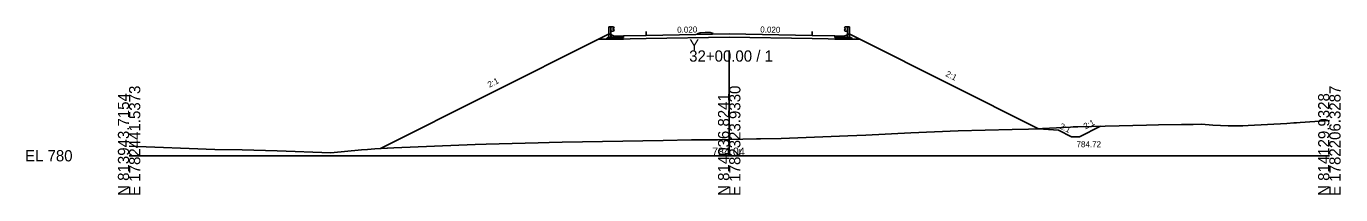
# Model space of a CAD drawing. Extents: x -12583 to 5303, y -44 to 25667.
# Drawn here: x 1974.3 to 2302.8, y 2490.3 to 2532.3 of the extents above; entities that cross this region are included whole.
import ezdxf

# ---------------------------------------------------------------- set-up
doc = ezdxf.new("R2010")
doc.units = 0
for name, color, linetype in [('Exist Cross Section Cell', 7, 'Continuous'), ('Exist XS Center Line Elevation Label', 7, 'Continuous'), ('Exist XS Ground Line', 7, 'Continuous'), ('Prop Conc 5in Monolithic Surface Mount Island', 7, 'Continuous'), ('Prop XS DDE', 7, 'Continuous'), ('Prop XS Ditch Standard Text', 7, 'Continuous'), ('Prop XS Dump Level', 7, 'Continuous'), ('Prop XS Earthwork Shape', 7, 'Continuous'), ('Prop XS EOT Tick Mark', 7, 'Continuous'), ('Prop XS Finish Grade', 7, 'Continuous'), ('Prop XS Finish Grade CurbGutter', 7, 'Continuous'), ('Prop XS Finish Grade Earthwork', 7, 'Continuous'), ('Prop XS Finish Grade Paved Shoulder', 7, 'Continuous'), ('Prop XS Finish Grade Pavement', 7, 'Continuous'), ('Prop XS Guardrail', 7, 'Continuous'), ('Prop XS Pvmt Edge Slope', 7, 'Continuous'), ('Prop XS SE Text', 7, 'Continuous'), ('Prop XS Side Slope Text', 7, 'Continuous'), ('Prop XS Subgrade CurbGutter', 7, 'Continuous'), ('Prop XS Subgrade Earthwork', 7, 'Continuous')]:
    doc.layers.add(name, color=color, linetype=linetype)

msp = doc.modelspace()

# ---------------------------------------------------------------- linework, layer by layer
at = {"layer": 'Exist Cross Section Cell'}
for p, q in [((2150, 2500), (2150, 2526.26)), ((2000, 2500), (2150, 2500)), ((2150, 2500), (2300, 2500))]:
    msp.add_line(p, q, dxfattribs=at)
at = {"layer": 'Exist XS Ground Line'}
for p, q in [((2224.82, 2506.63), (2235.29, 2507.15)), ((2235.29, 2507.15), (2235.97, 2507.18)), ((2235.97, 2507.18), (2237.13, 2507.22)), ((2237.13, 2507.22), (2254.26, 2507.62)), ((2254.26, 2507.62), (2257.3, 2507.71)), ((2257.3, 2507.71), (2263.07, 2507.76)), ((2263.07, 2507.76), (2265.97, 2507.81)), ((2265.97, 2507.81), (2268.01, 2507.89)), ((2268.01, 2507.89), (2270.89, 2507.65)), ((2270.89, 2507.65), (2274.72, 2507.45)), ((2274.72, 2507.45), (2276.53, 2507.48)), ((2276.53, 2507.48), (2278.36, 2507.47)), ((2278.36, 2507.47), (2279.67, 2507.55)), ((2279.67, 2507.55), (2289.38, 2508.06)), ((2289.38, 2508.06), (2291.13, 2508.17)), ((2291.13, 2508.17), (2291.75, 2508.2)), ((2291.75, 2508.2), (2292.69, 2508.26)), ((2292.69, 2508.26), (2300, 2508.75)), ((2108.23, 2503.35), (2133.51, 2503.8)), ((2133.51, 2503.8), (2140.57, 2503.94)), ((2140.57, 2503.94), (2147.06, 2503.97)), ((2147.06, 2503.97), (2150, 2504.04)), ((2150, 2504.04), (2156.84, 2504.18)), ((2156.84, 2504.18), (2157.79, 2504.19)), ((2157.79, 2504.19), (2163, 2504.32)), ((2163, 2504.32), (2179.65, 2504.95)), ((2179.65, 2504.95), (2184.13, 2505.17)), ((2184.13, 2505.17), (2195.43, 2505.7)), ((2195.43, 2505.7), (2207.25, 2506.25)), ((2207.25, 2506.25), (2220.73, 2506.52)), ((2220.73, 2506.52), (2224.82, 2506.63)), ((2000, 2502.37), (2021.46, 2501.59)), ((2021.46, 2501.59), (2028.25, 2501.45)), ((2028.25, 2501.45), (2037, 2501.25)), ((2037, 2501.25), (2050.41, 2500.71)), ((2050.41, 2500.71), (2058.08, 2501.45)), ((2058.08, 2501.45), (2059.63, 2501.58)), ((2059.63, 2501.58), (2061.4, 2501.74)), ((2061.4, 2501.74), (2066.19, 2502)), ((2066.19, 2502), (2086.5, 2502.8)), ((2086.5, 2502.8), (2089.25, 2502.88)), ((2089.25, 2502.88), (2102.23, 2503.22)), ((2102.23, 2503.22), (2105.03, 2503.27)), ((2105.03, 2503.27), (2108.23, 2503.35))]:
    msp.add_line(p, q, dxfattribs=at)
at = {"layer": 'Prop Conc 5in Monolithic Surface Mount Island'}
for p, q in [((2142, 2530.4), (2142.74, 2530.67)), ((2142, 2530.24), (2142, 2530.4)), ((2142.74, 2530.67), (2143.99, 2530.72)), ((2145.24, 2530.72), (2143.99, 2530.72)), ((2146, 2530.48), (2145.24, 2530.72)), ((2146, 2530.32), (2146, 2530.48))]:
    msp.add_line(p, q, dxfattribs=at)
at = {"layer": 'Prop XS DDE'}
for p, q in [((2227.32, 2506.75), (2232.32, 2506.34)), ((2242.82, 2507.35), (2237.55, 2504.72)), ((2232.32, 2506.34), (2235.55, 2504.72)), ((2235.55, 2504.72), (2237.55, 2504.72))]:
    msp.add_line(p, q, dxfattribs=at)
at = {"layer": 'Prop XS Dump Level'}
for p, q in [((2129.25, 2529.98), (2150, 2530.4)), ((2150, 2530.4), (2170.75, 2529.98))]:
    msp.add_line(p, q, dxfattribs=at)
at = {"layer": 'Prop XS Earthwork Shape'}
msp.add_lwpolyline([(2174.75, 2529.11), (2176.42, 2529.07), (2180.81, 2529.07), (2182.68, 2529.07), (2227.32, 2506.75), (2224.82, 2506.63), (2220.73, 2506.52), (2207.25, 2506.25), (2195.43, 2505.7), (2184.13, 2505.17), (2179.65, 2504.95), (2163, 2504.32), (2157.79, 2504.19), (2156.84, 2504.18), (2150, 2504.04), (2147.06, 2503.97), (2140.57, 2503.94), (2133.51, 2503.8), (2108.23, 2503.35), (2105.03, 2503.27), (2102.23, 2503.22), (2089.25, 2502.88), (2086.5, 2502.8), (2066.19, 2502), (2062.8, 2501.82), (2117.32, 2529.07), (2119.19, 2529.07), (2123.58, 2529.07), (2125.25, 2529.11), (2129.25, 2529.19), (2150, 2529.6), (2170.75, 2529.19)], close=True, dxfattribs=at)
at = {"layer": 'Prop XS EOT Tick Mark'}
for p, q in [((2129.25, 2529.98), (2129.25, 2530.98)), ((2170.75, 2529.98), (2170.75, 2530.98))]:
    msp.add_line(p, q, dxfattribs=at)
at = {"layer": 'Prop XS Finish Grade'}
for p, q in [((2117.32, 2529.07), (2119.98, 2530.4)), ((2120.56, 2530.11), (2119.98, 2530.4)), ((2179.44, 2530.11), (2180.02, 2530.4)), ((2182.68, 2529.07), (2180.02, 2530.4))]:
    msp.add_line(p, q, dxfattribs=at)
at = {"layer": 'Prop XS Finish Grade CurbGutter'}
for p, q in [((2121.25, 2529.77), (2120.56, 2530.11)), ((2123.58, 2529.87), (2121.25, 2529.77)), ((2176.42, 2529.87), (2178.75, 2529.77)), ((2178.75, 2529.77), (2179.44, 2530.11))]:
    msp.add_line(p, q, dxfattribs=at)
at = {"layer": 'Prop XS Finish Grade Earthwork'}
for p, q in [((2117.32, 2529.07), (2062.8, 2501.82)), ((2182.68, 2529.07), (2227.32, 2506.75))]:
    msp.add_line(p, q, dxfattribs=at)
at = {"layer": 'Prop XS Finish Grade Paved Shoulder'}
for p, q in [((2129.25, 2529.98), (2123.58, 2529.87)), ((2170.75, 2529.98), (2176.42, 2529.87))]:
    msp.add_line(p, q, dxfattribs=at)
at = {"layer": 'Prop XS Finish Grade Pavement'}
for p, q in [((2129.25, 2529.98), (2150, 2530.4)), ((2150, 2530.4), (2170.75, 2529.98)), ((2150, 2530.4), (2170.75, 2529.98))]:
    msp.add_line(p, q, dxfattribs=at)
at = {"layer": 'Prop XS Guardrail'}
for p, q in [((2119.93, 2532.17), (2120.43, 2532.17)), ((2119.93, 2529.67), (2119.93, 2532.17)), ((2120.43, 2532.17), (2120.93, 2532.17)), ((2120.43, 2532.17), (2120.43, 2529.67)), ((2120.93, 2531.03), (2120.43, 2531.03)), ((2120.93, 2532.17), (2121.22, 2531.97)), ((2121.22, 2531.85), (2120.93, 2531.65)), ((2120.93, 2531.65), (2120.93, 2531.55)), ((2120.93, 2531.55), (2121.22, 2531.35)), ((2121.22, 2531.23), (2120.93, 2531.03)), ((2121.22, 2531.97), (2121.25, 2531.91)), ((2121.25, 2531.91), (2121.22, 2531.85)), ((2121.22, 2531.35), (2121.25, 2531.29)), ((2121.25, 2531.29), (2121.22, 2531.23)), ((2178.78, 2531.97), (2178.75, 2531.91)), ((2178.75, 2531.91), (2178.78, 2531.85)), ((2178.78, 2531.35), (2178.75, 2531.29)), ((2178.75, 2531.29), (2178.78, 2531.23)), ((2179.07, 2532.17), (2178.78, 2531.97)), ((2178.78, 2531.85), (2179.07, 2531.65)), ((2179.07, 2531.55), (2178.78, 2531.35)), ((2178.78, 2531.23), (2179.07, 2531.03)), ((2179.57, 2532.17), (2179.07, 2532.17)), ((2179.07, 2531.65), (2179.07, 2531.55)), ((2179.07, 2531.03), (2179.57, 2531.03)), ((2180.07, 2532.17), (2179.57, 2532.17)), ((2179.57, 2532.17), (2179.57, 2529.67)), ((2180.07, 2529.67), (2180.07, 2532.17))]:
    msp.add_line(p, q, dxfattribs=at)
at = {"layer": 'Prop XS Pvmt Edge Slope'}
for p, q in [((2119.56, 2529.45), (2119.19, 2529.07)), ((2120.56, 2529.45), (2119.56, 2529.45)), ((2179.44, 2529.45), (2180.44, 2529.45)), ((2180.44, 2529.45), (2180.81, 2529.07))]:
    msp.add_line(p, q, dxfattribs=at)
at = {"layer": 'Prop XS Subgrade CurbGutter'}
for p, q in [((2120.56, 2529.45), (2120.56, 2530.11)), ((2123.58, 2529.87), (2123.58, 2529.45)), ((2176.42, 2529.87), (2176.42, 2529.45)), ((2179.44, 2529.45), (2179.44, 2530.11)), ((2123.58, 2529.45), (2120.56, 2529.45)), ((2176.42, 2529.45), (2179.44, 2529.45))]:
    msp.add_line(p, q, dxfattribs=at)
at = {"layer": 'Prop XS Subgrade Earthwork'}
for p, q in [((2119.19, 2529.07), (2117.32, 2529.07)), ((2123.58, 2529.07), (2119.19, 2529.07)), ((2125.25, 2529.11), (2123.58, 2529.07)), ((2129.25, 2529.19), (2125.25, 2529.11)), ((2150, 2529.6), (2129.25, 2529.19)), ((2170.75, 2529.19), (2150, 2529.6)), ((2170.75, 2529.19), (2174.75, 2529.11)), ((2174.75, 2529.11), (2176.42, 2529.07)), ((2176.42, 2529.08), (2176.42, 2529.07)), ((2176.42, 2529.07), (2180.81, 2529.07)), ((2180.81, 2529.07), (2182.68, 2529.07))]:
    msp.add_line(p, q, dxfattribs=at)

# ---------------------------------------------------------------- texts
at = {"layer": 'Exist Cross Section Cell'}
for s, p in [('Y', (2140, 2526.26)), ('32+00.00 / 1', (2140, 2523.46)), ('EL 780', (1974, 2498.6))]:
    msp.add_text(s, height=2.8, dxfattribs=at).set_placement(p)
for s, p in [('E 1782441.5373', (2002.8, 2490)), ('E 1782323.9330', (2152.8, 2490)), ('E 1782206.3287', (2302.8, 2490)), ('N 813943.7154', (2000, 2490)), ('N 814036.8241', (2150, 2490)), ('N 814129.9328', (2300, 2490))]:
    msp.add_text(s, height=2.8, rotation=90, dxfattribs=at).set_placement(p)
at = {"layer": 'Exist XS Center Line Elevation Label'}
msp.add_text('784.04', height=2, dxfattribs=at).set_placement((2145.72, 2500.04))
at = {"layer": 'Prop XS Ditch Standard Text'}
msp.add_text('784.72', height=1.5, dxfattribs=at).set_placement((2236.8, 2502.12))
at = {"layer": 'Prop XS Dump Level'}
msp.add_text('Case2', height=0.04, dxfattribs=at).set_placement((2176.42, 2529.83))
at = {"layer": 'Prop XS SE Text'}
for rotation, p in [(1.1458, (2137, 2530.64)), (358.8542, (2157.75, 2530.74)), (358.8542, (2157.75, 2530.74))]:
    msp.add_text('0.020', height=1.5, rotation=rotation, dxfattribs=at).set_placement(p)
at = {"layer": 'Prop XS Side Slope Text'}
for rotation, p in [(333.4349, (2203.94, 2519.92)), (26.5651, (2090.08, 2516.93)), (333.4349, (2232.39, 2506.89)), (26.5651, (2239.03, 2506.56))]:
    msp.add_text('2:1', height=1.5, rotation=rotation, dxfattribs=at).set_placement(p)

doc.saveas('drawing.dxf')
